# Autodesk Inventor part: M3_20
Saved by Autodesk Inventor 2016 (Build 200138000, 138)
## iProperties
Created: 2015-11
Part Number: M3_20
Material: Generic
Document SubType Name: Modeling
Designer: John
Density: 1 g/cm^3
Appearance: Default
Author: John
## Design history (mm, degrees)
feature "Base1"
body "Solid1"
